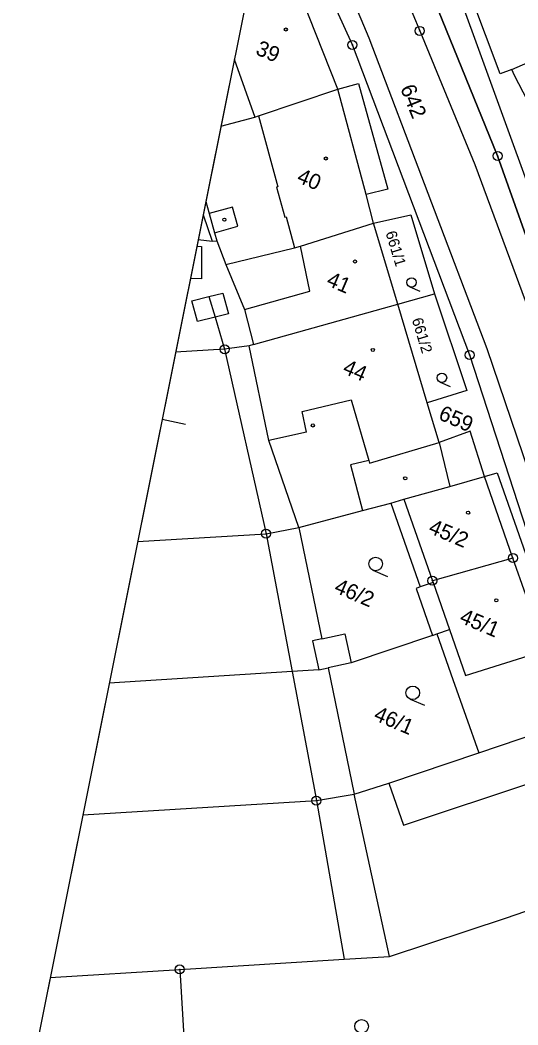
# Model space of a CAD drawing. Extents: x -548552 to -543113, y -1131925 to -1123599.
# Drawn here: x -548249.7 to -548194.6, y -1130640 to -1130528.9 of the extents above; entities that cross this region are included whole.
import ezdxf

# ---------------------------------------------------------------- set-up
doc = ezdxf.new("R2010")
doc.units = 0
for name, color, linetype in [('Hranice parcel', 7, 'Continuous'), ('Parcelní čísla', 7, 'Continuous'), ('Profile', 7, 'Continuous'), ('Vnitřní kresba', 7, 'Continuous'), ('Věcná břemena k části', 7, 'Continuous'), ('Značky bodu BP', 7, 'Continuous'), ('Značky budov', 7, 'Continuous'), ('Značky kultur', 7, 'Continuous')]:
    doc.layers.add(name, color=color, linetype=linetype)

msp = doc.modelspace()

# ---------------------------------------------------------------- linework, layer by layer
at = {"layer": 'Hranice parcel'}
for p, q in [((-548214.56, -1130536.52), (-548219.75, -1130523.36)), ((-548195.32, -1130534.33), (-548185.98, -1130530.29)), ((-548207.91, -1130560.28), (-548210.6, -1130551.33)), ((-548227.93, -1130553.3), (-548226.94, -1130555.91)), ((-548207.91, -1130560.28), (-548203.86, -1130559.15)), ((-548223.88, -1130564.76), (-548207.91, -1130560.28)), ((-548204.66, -1130571.22), (-548207.91, -1130560.28)), ((-548223.88, -1130564.76), (-548224.35, -1130564.89)), ((-548195.19, -1130588.38), (-548198.33, -1130579.36)), ((-548208.71, -1130582.3), (-548205.44, -1130591.58)), ((-548216.65, -1130600.76), (-548215.64, -1130600.53)), ((-548215.64, -1130600.53), (-548212.75, -1130614.49)), ((-548198.97, -1130609.93), (-548188.87, -1130606.51)), ((-548208.83, -1130632.44), (-548212.75, -1130614.49)), ((-548246.37, -1130634.79), (-548232.04, -1130633.89)), ((-548232.04, -1130633.89), (-548230.94, -1130651.62))]:
    msp.add_line(p, q, dxfattribs=at)
for points in [[(-548184.94, -1130577.46), (-548196.88, -1130543.9), (-548213.09, -1130504.06), (-548217.99, -1130493.22)], [(-548170.57, -1130654.95), (-548182.95, -1130618.21), (-548199.97, -1130565.92), (-548212.95, -1130531.61), (-548221.62, -1130512.49), (-548221.78, -1130512.11)], [(-548195.32, -1130534.33), (-548196.6, -1130534.81), (-548201.58, -1130521.53), (-548203.45, -1130516.53)], [(-548186.97, -1130547.77), (-548187.62, -1130546.47), (-548188.76, -1130547.05), (-548195.03, -1130534.99), (-548195.32, -1130534.33)], [(-548227.49, -1130540.59), (-548223.72, -1130539.59), (-548223.32, -1130539.45), (-548214.56, -1130536.52)], [(-548210.6, -1130551.33), (-548211.44, -1130548.15), (-548214.56, -1130536.52)], [(-548229.16, -1130548.93), (-548228.78, -1130550.28), (-548228.18, -1130552.41), (-548227.93, -1130553.3)], [(-548210.6, -1130551.33), (-548206.48, -1130550.41), (-548203.86, -1130559.15)], [(-548226.94, -1130555.91), (-548219.36, -1130554.05), (-548218.7, -1130553.89), (-548210.6, -1130551.33)], [(-548230.16, -1130553.89), (-548229.62, -1130553.91), (-548229.65, -1130557.48)], [(-548230, -1130553.13), (-548228.46, -1130553.31), (-548227.93, -1130553.3)], [(-548226.94, -1130555.91), (-548224.89, -1130560.89), (-548223.88, -1130564.76)], [(-548229.65, -1130557.48), (-548230.87, -1130557.46)], [(-548203.86, -1130559.15), (-548200.28, -1130569.86), (-548204.66, -1130571.22)], [(-548224.35, -1130564.89), (-548227.08, -1130565.29), (-548232.51, -1130565.61)], [(-548218.86, -1130585.01), (-548222.2, -1130575.38), (-548224.35, -1130564.89)], [(-548198.33, -1130579.36), (-548199.92, -1130574.34), (-548203.36, -1130575.6), (-548204.66, -1130571.22)], [(-548208.71, -1130582.3), (-548207.27, -1130581.88), (-548202.18, -1130580.45), (-548198.33, -1130579.36)], [(-548218.86, -1130585.01), (-548211.81, -1130583.13), (-548208.71, -1130582.3)], [(-548236.71, -1130586.56), (-548222.5, -1130585.69), (-548218.86, -1130585.01)], [(-548218.86, -1130585.01), (-548216.31, -1130597.31), (-548217.36, -1130597.54), (-548216.65, -1130600.76)], [(-548195.19, -1130588.38), (-548204.1, -1130590.89), (-548204.03, -1130591.08), (-548205.44, -1130591.58)], [(-548188.87, -1130606.51), (-548191.63, -1130598.6), (-548193.78, -1130592.44), (-548195.19, -1130588.38)], [(-548205.44, -1130591.58), (-548205.91, -1130591.74), (-548204.09, -1130596.94)], [(-548204.09, -1130596.94), (-548213.09, -1130599.98), (-548215.64, -1130600.53)], [(-548204.09, -1130596.94), (-548203.61, -1130596.78), (-548201.84, -1130601.81), (-548198.97, -1130609.93)], [(-548216.65, -1130600.76), (-548219.61, -1130600.94), (-548239.84, -1130602.21)], [(-548212.75, -1130614.49), (-548208.93, -1130613.3), (-548198.97, -1130609.93)], [(-548242.76, -1130616.79), (-548216.93, -1130615.21), (-548212.75, -1130614.49)], [(-548208.83, -1130632.44), (-548195.9, -1130628.19), (-548192.8, -1130627.11)], [(-548232.04, -1130633.89), (-548213.84, -1130632.75), (-548208.83, -1130632.44)]]:
    msp.add_lwpolyline(points, dxfattribs=at)
at = {"layer": 'Profile'}
for p, q in [((-548215.64, -1130481.48), (-548249.7, -1130651.36)), ((-548226.59, -1130536.08), (-548249.7, -1130651.36)), ((-548231.41, -1130573.59), (-548234, -1130573.07))]:
    msp.add_line(p, q, dxfattribs=at)
at = {"layer": 'Vnitřní kresba'}
for p, q in [((-548215.68, -1130505.18), (-548205.5, -1130530.06)), ((-548219.33, -1130511.51), (-548211.12, -1130530.83)), ((-548205.5, -1130530.06), (-548199.39, -1130544.84)), ((-548211.12, -1130530.83), (-548198.09, -1130565.2)), ((-548226.01, -1130533.2), (-548223.72, -1130539.59)), ((-548214.56, -1130536.52), (-548212.26, -1130535.88)), ((-548212.26, -1130535.88), (-548209.02, -1130547.59)), ((-548223.32, -1130539.45), (-548221.18, -1130547.32)), ((-548199.39, -1130544.84), (-548182.92, -1130589.58)), ((-548221.18, -1130547.32), (-548221.33, -1130547.36)), ((-548221.33, -1130547.36), (-548220.43, -1130550.67)), ((-548209.02, -1130547.59), (-548211.44, -1130548.15)), ((-548226.22, -1130549.55), (-548228.78, -1130550.28)), ((-548225.61, -1130551.68), (-548226.22, -1130549.55)), ((-548229.46, -1130550.42), (-548228.46, -1130553.31)), ((-548220.43, -1130550.67), (-548220.28, -1130550.63)), ((-548220.28, -1130550.63), (-548219.36, -1130554.05)), ((-548228.18, -1130552.41), (-548225.61, -1130551.68)), ((-548217.64, -1130558.87), (-548218.7, -1130553.89)), ((-548230.7, -1130559.91), (-548228.82, -1130559.46)), ((-548228.82, -1130559.46), (-548227.27, -1130559.09)), ((-548228.82, -1130559.46), (-548228.14, -1130561.74)), ((-548227.27, -1130559.09), (-548226.63, -1130561.38)), ((-548224.89, -1130560.89), (-548217.64, -1130558.87)), ((-548230.06, -1130562.2), (-548230.7, -1130559.91)), ((-548228.14, -1130561.74), (-548230.06, -1130562.2)), ((-548226.63, -1130561.38), (-548228.14, -1130561.74)), ((-548228.14, -1130561.74), (-548227.08, -1130565.29)), ((-548227.08, -1130565.29), (-548222.5, -1130585.69)), ((-548198.09, -1130565.2), (-548190.42, -1130587.8)), ((-548218.5, -1130572.15), (-548213.07, -1130570.87)), ((-548213.07, -1130570.87), (-548211.13, -1130577.59)), ((-548218.03, -1130574.44), (-548218.5, -1130572.15)), ((-548218.03, -1130574.44), (-548222.2, -1130575.38)), ((-548211.04, -1130577.9), (-548203.36, -1130575.6)), ((-548203.36, -1130575.6), (-548202.18, -1130580.45)), ((-548211.13, -1130577.59), (-548213.15, -1130578.07)), ((-548213.15, -1130578.07), (-548211.81, -1130583.13)), ((-548211.13, -1130577.59), (-548211.04, -1130577.9)), ((-548198.33, -1130579.36), (-548196.95, -1130578.96)), ((-548196.95, -1130578.96), (-548192.37, -1130591.96)), ((-548207.27, -1130581.88), (-548204.1, -1130590.89)), ((-548222.5, -1130585.69), (-548219.61, -1130600.94)), ((-548204.03, -1130591.08), (-548202.2, -1130596.3)), ((-548203.61, -1130596.78), (-548202.2, -1130596.3)), ((-548202.2, -1130596.3), (-548200.42, -1130601.37)), ((-548216.31, -1130597.31), (-548213.79, -1130596.76)), ((-548213.79, -1130596.76), (-548213.09, -1130599.98)), ((-548200.42, -1130601.37), (-548191.63, -1130598.6)), ((-548219.61, -1130600.94), (-548216.93, -1130615.21)), ((-548208.93, -1130613.3), (-548207.28, -1130617.94)), ((-548207.28, -1130617.94), (-548192.76, -1130613.1)), ((-548216.93, -1130615.21), (-548213.84, -1130632.75))]:
    msp.add_line(p, q, dxfattribs=at)
at = {"layer": 'Věcná břemena k části'}
msp.add_lwpolyline([(-548218, -1130493.22), (-548216.91, -1130495.61), (-548216.12, -1130496.65), (-548214.82, -1130500.24), (-548213.09, -1130504.06), (-548196.88, -1130543.9), (-548184.94, -1130577.46), (-548183.94, -1130577.01), (-548183.46, -1130576.8), (-548183.22, -1130576.69), (-548192.21, -1130550.68), (-548212.57, -1130494.71), (-548217.1, -1130488.75)], dxfattribs=at)
at = {"layer": 'Značky bodu BP'}
for centre, radius in [((-548205.5, -1130530.06), 0.5), ((-548205.5, -1130530.06), 0.0303), ((-548212.95, -1130531.61), 0.5), ((-548212.95, -1130531.61), 0.0303), ((-548196.88, -1130543.9), 0.5), ((-548196.88, -1130543.9), 0.0303), ((-548227.08, -1130565.29), 0.5), ((-548227.08, -1130565.29), 0.0303), ((-548199.97, -1130565.92), 0.5), ((-548199.97, -1130565.92), 0.0303), ((-548222.5, -1130585.69), 0.5), ((-548222.5, -1130585.69), 0.0303), ((-548195.19, -1130588.38), 0.5), ((-548195.19, -1130588.38), 0.0303), ((-548204.1, -1130590.89), 0.5), ((-548204.1, -1130590.89), 0.0303), ((-548216.93, -1130615.21), 0.5), ((-548216.93, -1130615.21), 0.0303), ((-548232.04, -1130633.89), 0.5), ((-548232.04, -1130633.89), 0.0303)]:
    msp.add_circle(centre, radius, dxfattribs=at)
at = {"layer": 'Značky budov'}
for centre in [(-548220.31, -1130529.91), (-548215.88, -1130544.18), (-548227.1, -1130550.95), (-548212.66, -1130555.57), (-548210.69, -1130565.36), (-548217.32, -1130573.71), (-548207.1, -1130579.56), (-548200.15, -1130583.36), (-548197.03, -1130593.05)]:
    msp.add_circle(centre, 0.175, dxfattribs=at)
at = {"layer": 'Značky kultur'}
for p, q in [((-548206.6, -1130558.38), (-548205.48, -1130558.86)), ((-548203.24, -1130568.92), (-548202.12, -1130569.4)), ((-548210.67, -1130589.72), (-548209.06, -1130590.41)), ((-548206.57, -1130603.98), (-548204.96, -1130604.67))]:
    msp.add_line(p, q, dxfattribs=at)
for centre, radius in [((-548206.4, -1130557.89), 0.525), ((-548203.04, -1130568.44), 0.525), ((-548210.38, -1130589.03), 0.75), ((-548206.27, -1130603.29), 0.75), ((-548211.93, -1130640.18), 0.75)]:
    msp.add_circle(centre, radius, dxfattribs=at)

# ---------------------------------------------------------------- texts
at = {"layer": 'Parcelní čísla'}
for s, height, rotation, p in [('39', 1.7, 336.8058, (-548223.76, -1130532.61)), ('642', 1.7, 291.8058, (-548207.68, -1130536.39)), ('40', 1.7, 336.8058, (-548219.2, -1130546.75)), ('661/1', 1.2, 286.8058, (-548209.29, -1130552.39)), ('41', 1.7, 336.8058, (-548215.92, -1130558.17)), ('661/2', 1.2, 286.8058, (-548206.38, -1130562)), ('44', 1.7, 336.8058, (-548214.13, -1130567.88)), ('659', 1.7, 336.8058, (-548203.54, -1130572.99)), ('45/2', 1.7, 336.8058, (-548204.64, -1130585.55)), ('46/2', 1.7, 336.8058, (-548215.07, -1130592.12)), ('45/1', 1.7, 336.8058, (-548201.21, -1130595.46)), ('46/1', 1.7, 336.8058, (-548210.7, -1130606.24))]:
    msp.add_text(s, height=height, rotation=rotation, dxfattribs=at).set_placement(p)

doc.saveas('drawing.dxf')
